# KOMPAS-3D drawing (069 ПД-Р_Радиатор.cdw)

Views: Вид 1
Referenced files: graphic.tdp
Referenced files in D:\100_Работа\003_КД\003_Проекты\СхемыУстПриборов\: КТС-Б_Труба_Ду100.cdw
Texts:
  ПСПД-0000-2015
  Узел учёта тепловой энергии и теплоносителя
  Кремляков А.И.
  Служба проектно-сметная
  ПромСервисА.И.
  Лит-Масса-Масштаб
  Материал-Предприятие
  Title Specification
  Body Specification ( left align )
  Body Specificaton ( centered )
  ГОСТ 16037-80-У17-ЗН- 4
  Размеры для справок.
  Допустимое   угловое  смещение   деталей поз. 1, 2, 3
  относительно фланцев и номинального положения  2 .
  Сварные швы проверить внешним осмотром по ГОСТ 3242-79.
  Трещины, прожоги, свищи, раковины, непровары не допускаются.
  Измерительный участок испытать на прочность и
  герметичность пробным гидравлическим давлением Pпр=2,0 МПа в
  течение 30 мин. Течь, потение, видимые остаточные деформации не
  допускаются. Испытание произвести без датчика давления поз.1 .
  ПД-Р, И, (0...1,6 МПа),
  ПД-Р, И, (0...1,6 МПа),0.5, 4...20 мА, М20х1,5
  Датчик давления
  мод. ПД-Р
  Датчик давления  /  мод. ПД-Р
  или
  аналог
  или  аналог
  ТУ 3712-005-05749381-94
  11б18бк (11б38бк) ТУ 3712-005-05749381-94
  Кран трёхходовой
  DN15; PN16;
  Кран трёхходовой  DN15; PN16; Tmax=150@1~C
  Резьба
  неоцинкованная
  из трубы по
  ГОСТ 3262-75
  Ду15
  Резьба  неоцинкованная из трубы по  ГОСТ 3262-75  Ду15
  ТУ 374-00145630722-2003
  11б27п1 ТУ 374-00145630722-2003
  Кран шаровый
  м/м DN15; PN30
  Кран шаровый  м/м DN15; PN30
  ООО "ПОИНТ"
  ТУ  РБ 390184271,013-2009
  ООО "ПОИНТ" Р1-G1/2-G1/2-120 ТУ  РБ 390184271,013-2009
  Радиатор-
  охладитель
  Радиатор- охладитель
  Груп. спецификация (менее 3 исполн.) ГОСТ 2.113-75.
  Груп. специфик. Первый лист. ГОСТ 2.113-75 Ф.5.
  Поз.
  Кол. на
  Приме-
  чание
  Номер исполнения
  Таблица спецификации
  Нач. отд.
  ЗАО "ПромСервис"
  г. Димитровград
  Узел учёта тепловой энергии и
  теплоносителя
  ПСПД-0093-2014-
  Схема установки
  датчика давления мод. ПД-Р с радиатором-охлодителем
Dimensions and other numbers on the sheet: 6; 3; 2; 1; 65,63; 5; 0.5, 4...20 мА, М20х1,5; 11б18бк (11б38бк); 11б27п1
